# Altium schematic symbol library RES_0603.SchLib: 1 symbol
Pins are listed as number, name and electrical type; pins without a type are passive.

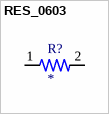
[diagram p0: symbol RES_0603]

## RES_0603
designator R?
1% 0.1W; MP: 1-2176071-4
footprint RESC1608X50N
pins: 1, 2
